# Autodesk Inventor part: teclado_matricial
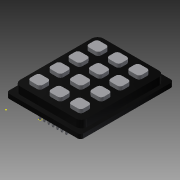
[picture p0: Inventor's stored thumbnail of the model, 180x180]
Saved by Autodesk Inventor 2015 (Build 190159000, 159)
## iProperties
Created: 2016-06
Part Number: teclado_matricial
Material: Genérico
Document SubType Name: Modeling
Designer: Diego
Density: 1 g/cm^3
Appearance: Valor por defecto
Author: Diego
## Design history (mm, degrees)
sketch "Boceto1"
  geometry: L1 (0, 0)-(51, 0); L2 (51, 0)-(51, 64); L3 (51, 64)-(0, 64); L4 (0, 64)-(0, 0)
  constraints: 8 end point, 2 parallel, 1 horizontal, 1 perpendicular
  dimensions: "d0" = 51 distance of L3.end L2.end; "d1" = 64 distance of L2.end L1.end
extrude "Extrusión1" new body sketch "Boceto1" distance "d2" = 3; taper "d3" = 0 deg
fillet "Empalme1" dims "d4" = 2
fillet "Empalme2" dims "d5" = 2
sketch "Boceto2"
  geometry: L1 (2.5, 32)-(2.5, 3.163); L2 (2.5, 3.163)-(48.5, 3.163); L3 (48.5, 3.163)-(48.5, 60.163); L4 (48.5, 60.163)-(2.5, 60.163); L5 (2.5, 60.163)-(2.5, 3.163); A1 r 2 centre (49, 62) between (51, 62) and (49, 64) reference; A2 r 2 centre (49, 2) between (49, 0) and (51, 2) reference; A3 r 2 centre (2, 62) between (2, 64) and (0, 62) reference; 1 further point
  constraints: 10 end point, 2 parallel, 1 horizontal, 1 perpendicular
  dimensions: "d7" = 46 distance of L4.end L3.end; "d8" = 57 distance of L3.end L2.end
extrude "Extrusión2" join sketch "Boceto2" distance "d9" = 5; taper "d10" = 0 deg
sketch "Boceto3" dims "d31" = 10, "d38" = 10
  geometry: L1 (2.5, 60.163)-(48.5, 60.163) reference; L2 (48.5, 3.163)-(2.5, 3.163) reference; L3 (2.5, 3.163)-(2.5, 60.163) reference; L4 (2.5, 31.663)-(48.5, 31.663); L5 (48.5, 60.163)-(48.5, 3.163) reference; L6 (25.5, 31.663)-(25.5, 38.163); L7 (21.25, 23.397)-(21.25, 26.913); L8 (23.25, 28.913)-(27.75, 28.913); L9 (29.75, 26.913)-(29.75, 23.413); L10 (27.75, 21.413)-(23.25, 21.413); L11 (41.75, 21.413)-(37.25, 21.413); L12 (43.75, 26.913)-(43.75, 23.413); L13 (37.25, 28.913)-(41.75, 28.913); L14 (35.25, 23.397)-(35.25, 26.913); L15 (27.75, 34.413)-(23.25, 34.413); L16 (29.75, 39.913)-(29.75, 36.413); L17 (23.25, 41.913)-(27.75, 41.913); L18 (21.25, 36.397)-(21.25, 39.913); L19 (41.75, 34.413)-(37.25, 34.413); L20 (43.75, 39.913)-(43.75, 36.413); L21 (37.25, 41.913)-(41.75, 41.913); L22 (35.25, 36.397)-(35.25, 39.913); L23 (27.75, 47.413)-(23.25, 47.413); L24 (29.75, 52.913)-(29.75, 49.413); L25 (23.25, 54.913)-(27.75, 54.913); L26 (21.25, 49.397)-(21.25, 52.913); L27 (41.75, 47.413)-(37.25, 47.413); L28 (43.75, 52.913)-(43.75, 49.413); L29 (37.25, 54.913)-(41.75, 54.913); L30 (35.25, 49.397)-(35.25, 52.913); L31 (35.25, 9.397)-(35.25, 12.913); L32 (41.75, 7.413)-(37.25, 7.413); L33 (37.25, 14.913)-(41.75, 14.913); L34 (43.75, 12.913)-(43.75, 9.413); L35 (21.25, 9.397)-(21.25, 12.913); L36 (23.25, 14.913)-(27.75, 14.913); L37 (29.75, 12.913)-(29.75, 9.413); L38 (27.75, 7.413)-(23.25, 7.413); L39 (13.75, 47.413)-(9.25, 47.413); L40 (15.75, 52.913)-(15.75, 49.413); L41 (7.25, 49.397)-(7.25, 52.913); L42 (9.25, 54.913)-(13.75, 54.913); L43 (7.25, 23.397)-(7.25, 26.913); L44 (9.25, 28.913)-(13.75, 28.913); L45 (15.75, 26.913)-(15.75, 23.413); L46 (13.75, 21.413)-(9.25, 21.413); L47 (11.5, 31.663)-(11.5, 38.163); L48 (13.75, 34.413)-(9.25, 34.413); L49 (15.75, 39.913)-(15.75, 36.413); L50 (9.25, 41.913)-(13.75, 41.913); L51 (7.25, 36.397)-(7.25, 39.913); L52 (15.75, 12.913)-(15.75, 9.413); L53 (9.25, 14.913)-(13.75, 14.913); L54 (13.75, 7.413)-(9.25, 7.413); L55 (7.25, 9.397)-(7.25, 12.913); L56 (6.5, 60.163)-(44.5, 60.163); L57 (48.5, 56.163)-(48.5, 7.163); L58 (44.5, 3.163)-(6.5, 3.163); L59 (2.5, 7.163)-(2.5, 56.163); A1 r 2 centre (23.25, 26.913) between (23.25, 28.913) and (21.25, 26.913); A2 r 2 centre (23.25, 23.413) between (21.25, 23.413) and (23.25, 21.413); A3 r 2 centre (27.75, 26.913) between (29.75, 26.913) and (27.75, 28.913); A4 r 2 centre (27.75, 23.413) between (27.75, 21.413) and (29.75, 23.413); A5 r 2 centre (41.75, 23.413) between (41.75, 21.413) and (43.75, 23.413); A6 r 2 centre (37.25, 23.413) between (35.25, 23.413) and (37.25, 21.413); A7 r 2 centre (37.25, 26.913) between (37.25, 28.913) and (35.25, 26.913); A8 r 2 centre (41.75, 26.913) between (43.75, 26.913) and (41.75, 28.913); A9 r 2 centre (27.75, 36.413) between (27.75, 34.413) and (29.75, 36.413); A10 r 2 centre (23.25, 36.413) between (21.25, 36.413) and (23.25, 34.413); A11 r 2 centre (23.25, 39.913) between (23.25, 41.913) and (21.25, 39.913); A12 r 2 centre (27.75, 39.913) between (29.75, 39.913) and (27.75, 41.913); A13 r 2 centre (41.75, 36.413) between (41.75, 34.413) and (43.75, 36.413); A14 r 2 centre (37.25, 36.413) between (35.25, 36.413) and (37.25, 34.413); A15 r 2 centre (37.25, 39.913) between (37.25, 41.913) and (35.25, 39.913); A16 r 2 centre (41.75, 39.913) between (43.75, 39.913) and (41.75, 41.913); A17 r 2 centre (27.75, 49.413) between (27.75, 47.413) and (29.75, 49.413); A18 r 2 centre (23.25, 49.413) between (21.25, 49.413) and (23.25, 47.413); A19 r 2 centre (23.25, 52.913) between (23.25, 54.913) and (21.25, 52.913); A20 r 2 centre (27.75, 52.913) between (29.75, 52.913) and (27.75, 54.913); A21 r 2 centre (41.75, 49.413) between (41.75, 47.413) and (43.75, 49.413); A22 r 2 centre (37.25, 49.413) between (35.25, 49.413) and (37.25, 47.413); A23 r 2 centre (37.25, 52.913) between (37.25, 54.913) and (35.25, 52.913); A24 r 2 centre (41.75, 52.913) between (43.75, 52.913) and (41.75, 54.913); A25 r 2 centre (37.25, 12.913) between (37.25, 14.913) and (35.25, 12.913); A26 r 2 centre (37.25, 9.413) between (35.25, 9.413) and (37.25, 7.413); A27 r 2 centre (41.75, 9.413) between (41.75, 7.413) and (43.75, 9.413); A28 r 2 centre (41.75, 12.913) between (43.75, 12.913) and (41.75, 14.913); A29 r 2 centre (23.25, 12.913) between (23.25, 14.913) and (21.25, 12.913); A30 r 2 centre (27.75, 12.913) between (29.75, 12.913) and (27.75, 14.913); A31 r 2 centre (23.25, 9.413) between (21.25, 9.413) and (23.25, 7.413); A32 r 2 centre (27.75, 9.413) between (27.75, 7.413) and (29.75, 9.413); A33 r 2 centre (13.75, 49.413) between (13.75, 47.413) and (15.75, 49.413); A34 r 2 centre (9.25, 49.413) between (7.25, 49.413) and (9.25, 47.413); A35 r 2 centre (13.75, 52.913) between (15.75, 52.913) and (13.75, 54.913); A36 r 2 centre (9.25, 52.913) between (9.25, 54.913) and (7.25, 52.913); A37 r 2 centre (9.25, 26.913) between (9.25, 28.913) and (7.25, 26.913); A38 r 2 centre (9.25, 23.413) between (7.25, 23.413) and (9.25, 21.413); A39 r 2 centre (13.75, 23.413) between (13.75, 21.413) and (15.75, 23.413); A40 r 2 centre (13.75, 26.913) between (15.75, 26.913) and (13.75, 28.913); A41 r 2 centre (13.75, 36.413) between (13.75, 34.413) and (15.75, 36.413); A42 r 2 centre (9.25, 36.413) between (7.25, 36.413) and (9.25, 34.413); A43 r 2 centre (9.25, 39.913) between (9.25, 41.913) and (7.25, 39.913); A44 r 2 centre (13.75, 39.913) between (15.75, 39.913) and (13.75, 41.913); A45 r 2 centre (13.75, 12.913) between (15.75, 12.913) and (13.75, 14.913); A46 r 2 centre (13.75, 9.413) between (13.75, 7.413) and (15.75, 9.413); A47 r 2 centre (9.25, 9.413) between (7.25, 9.413) and (9.25, 7.413); A48 r 2 centre (9.25, 12.913) between (9.25, 14.913) and (7.25, 12.913); A49 r 4 centre (6.5, 7.163) between (2.5, 7.163) and (6.5, 3.163); A50 r 4 centre (44.5, 7.163) between (44.5, 3.163) and (48.5, 7.163); A51 r 4 centre (44.5, 56.163) between (48.5, 56.163) and (44.5, 60.163); A52 r 4 centre (6.5, 56.163) between (6.5, 60.163) and (2.5, 56.163); 37 further points
  constraints: 116 point on circle, 110 end point, 64 point on line, 52 centre point, 15 tangent, 6 equal radius, 4 horizontal, 3 midpoint, 3 parallel, 3 vertical, 2 perpendicular, 267 other
  dimensions: "d15" = 8.5 distance of point (29.75, 21.413) point (21.25, 21.413); "d16" = 7.5 distance of point (29.75, 28.913) point (29.75, 21.413); "d20" = 14 distance of point (21.25, 21.413) point (35.25, 21.413); "d23" = 13 distance of point (21.25, 21.413) point (21.25, 34.413); "d28" = 14 distance of L14.start L31.start; "d35" = 14 distance of L23.start L39.start; "d41" = 4 radius of A49
extrude "Extrusión3" join sketch "Boceto3" distance "d42" = 2.5; taper "d43" = 0 deg
fillet "Empalme3" dims "d44" = 4
fillet "Empalme4" dims "d45" = 4
sketch "Boceto4" dims "d35" = 14, "d38" = 10
  geometry: L1 (-2, 0)-(-49, 0) reference; L2 (-25.5, 0)-(-25.5, 31.743); L3 (-14.434, 6)-(-36.434, 6); L4 (-36.434, 6)-(-36.434, 8); L5 (-36.434, 8)-(-14.434, 8); L6 (-14.434, 8)-(-14.434, 6); 1 further point
  constraints: 10 end point, 2 parallel, 1 horizontal, 1 midpoint, 1 perpendicular, 1 vertical
  dimensions: "d46" = 22 distance of L4.end L5.end; "d47" = 2 distance of L3.end L4.end
extrude "Extrusión4" join sketch "Boceto4" distance "d48" = 2.5; taper "d49" = 0 deg
sketch "Boceto5" dims "d61" = 10, "d68" = 10
  geometry: L1 (-36.434, 6)-(-14.434, 6) reference; L2 (-36.434, 8)-(-14.434, 8) reference; L3 (-24.784, 7)-(-24.784, 6.35); L4 (-24.784, 6.35)-(-26.084, 6.35); L5 (-26.084, 6.35)-(-26.084, 7.65); L6 (-26.084, 7.65)-(-24.784, 7.65); L7 (-24.784, 7.65)-(-24.784, 6.35); L8 (-25.434, 7)-(-15.828, 7); L9 (-21.784, 7)-(-21.784, 6.35); L10 (-21.784, 6.35)-(-23.084, 6.35); L11 (-23.084, 6.35)-(-23.084, 7.65); L12 (-23.084, 7.65)-(-21.784, 7.65); L13 (-21.784, 7.65)-(-21.784, 6.35); L14 (-18.784, 7)-(-18.784, 6.35); L15 (-18.784, 6.35)-(-20.084, 6.35); L16 (-20.084, 6.35)-(-20.084, 7.65); L17 (-20.084, 7.65)-(-18.784, 7.65); L18 (-18.784, 7.65)-(-18.784, 6.35); L19 (-15.784, 7)-(-15.784, 6.35); L20 (-15.784, 6.35)-(-17.084, 6.35); L21 (-17.084, 6.35)-(-17.084, 7.65); L22 (-17.084, 7.65)-(-15.784, 7.65); L23 (-15.784, 7.65)-(-15.784, 6.35); L24 (-27.784, 7)-(-27.784, 6.35); L25 (-27.784, 7.65)-(-27.784, 6.35); L26 (-27.784, 6.35)-(-29.084, 6.35); L27 (-29.084, 6.35)-(-29.084, 7.65); L28 (-29.084, 7.65)-(-27.784, 7.65); L29 (-30.784, 7)-(-30.784, 6.35); L30 (-30.784, 7.65)-(-30.784, 6.35); L31 (-30.784, 6.35)-(-32.084, 6.35); L32 (-32.084, 6.35)-(-32.084, 7.65); L33 (-32.084, 7.65)-(-30.784, 7.65); L34 (-33.784, 7)-(-33.784, 6.35); L35 (-33.784, 7.65)-(-33.784, 6.35); L36 (-33.784, 6.35)-(-35.084, 6.35); L37 (-35.084, 6.35)-(-35.084, 7.65); L38 (-35.084, 7.65)-(-33.784, 7.65); 7 further points
  constraints: 72 end point, 4 horizontal, 2 parallel, 1 perpendicular, 66 other
  dimensions: "d55" = 1.3 distance of L4.end L5.end; "d58" = 3 distance of L3.start L9.start; "d65" = 3 distance of L3.start L24.start
extrude "Extrusión5" join sketch "Boceto5" distance "d70" = 5; taper "d71" = 0 deg
fillet "Empalme5" dims "d72" = 0.2
sketch "Boceto6"
  geometry: 1 further point
node "Plano de trabajo1"
sketch "Boceto7" dims "d79" = 10
  geometry: L1 (-15.984, 7.65)-(-16.884, 7.65); L2 (-16.126, 6.691)-(-16.743, 6.691); L3 (-16.743, 6.691)-(-16.743, 7.309); L4 (-16.743, 7.309)-(-16.126, 7.309); L5 (-16.126, 7.309)-(-16.126, 6.691); L6 (-19.126, 6.691)-(-19.743, 6.691); L7 (-19.743, 7.309)-(-19.126, 7.309); L8 (-19.126, 7.309)-(-19.126, 6.691); L9 (-19.743, 6.691)-(-19.743, 7.309); L10 (-22.126, 6.691)-(-22.743, 6.691); L11 (-22.743, 7.309)-(-22.126, 7.309); L12 (-22.126, 7.309)-(-22.126, 6.691); L13 (-22.743, 6.691)-(-22.743, 7.309); L14 (-25.126, 6.691)-(-25.743, 6.691); L15 (-25.743, 7.309)-(-25.126, 7.309); L16 (-25.126, 7.309)-(-25.126, 6.691); L17 (-25.743, 6.691)-(-25.743, 7.309); L18 (-28.126, 6.691)-(-28.743, 6.691); L19 (-28.743, 7.309)-(-28.126, 7.309); L20 (-28.126, 7.309)-(-28.126, 6.691); L21 (-28.743, 6.691)-(-28.743, 7.309); L22 (-31.126, 6.691)-(-31.743, 6.691); L23 (-31.743, 7.309)-(-31.126, 7.309); L24 (-31.126, 7.309)-(-31.126, 6.691); L25 (-31.743, 6.691)-(-31.743, 7.309); L26 (-34.126, 6.691)-(-34.743, 6.691); L27 (-34.743, 7.309)-(-34.126, 7.309); L28 (-34.126, 7.309)-(-34.126, 6.691); L29 (-34.743, 6.691)-(-34.743, 7.309); 2 further points
  constraints: 58 end point, 2 horizontal, 2 parallel, 1 perpendicular, 48 other
  dimensions: "d76" = 3 distance of L3.end L7.start
feature "Solevación1" sketch "Boceto7" dims "d81" = 0, "d82" = 90 deg, "d83" = 0, "d84" = 90 deg
  node "Aristas1"
sketch "Boceto8" dims "d90" = 10
  geometry: L1 (-16.126, 6.691)-(-16.743, 6.691); L2 (-16.743, 6.691)-(-16.743, 7.309); L3 (-16.743, 7.309)-(-16.126, 7.309); L4 (-16.126, 7.309)-(-16.126, 6.691); L5 (-19.126, 6.691)-(-19.743, 6.691); L6 (-19.743, 6.691)-(-19.743, 7.309); L7 (-19.743, 7.309)-(-19.126, 7.309); L8 (-19.126, 7.309)-(-19.126, 6.691); L9 (-22.126, 6.691)-(-22.743, 6.691); L10 (-22.743, 6.691)-(-22.743, 7.309); L11 (-22.743, 7.309)-(-22.126, 7.309); L12 (-22.126, 7.309)-(-22.126, 6.691); L13 (-25.126, 6.691)-(-25.743, 6.691); L14 (-25.743, 6.691)-(-25.743, 7.309); L15 (-25.743, 7.309)-(-25.126, 7.309); L16 (-25.126, 7.309)-(-25.126, 6.691); L17 (-28.126, 6.691)-(-28.743, 6.691); L18 (-28.743, 6.691)-(-28.743, 7.309); L19 (-28.743, 7.309)-(-28.126, 7.309); L20 (-28.126, 7.309)-(-28.126, 6.691); L21 (-31.126, 6.691)-(-31.743, 6.691); L22 (-31.743, 6.691)-(-31.743, 7.309); L23 (-31.743, 7.309)-(-31.126, 7.309); L24 (-31.126, 7.309)-(-31.126, 6.691); L25 (-34.126, 6.691)-(-34.743, 6.691); L26 (-34.743, 6.691)-(-34.743, 7.309); L27 (-34.743, 7.309)-(-34.126, 7.309); L28 (-34.126, 7.309)-(-34.126, 6.691); 1 further point
  constraints: 56 end point, 2 horizontal, 2 parallel, 1 collinear, 1 perpendicular, 47 other
  dimensions: "d87" = 3 distance of L1.end L5.end
feature "Solevación2" sketch "Boceto8" dims "d92" = 0, "d93" = 90 deg, "d94" = 0, "d95" = 90 deg
  node "Aristas2"
sketch "Boceto9" dims "d101" = 10
  geometry: L1 (-19.743, 6.691)-(-19.583, 6.691) reference; L2 (-19.583, 6.691)-(-19.126, 6.691) reference; L3 (-19.126, 6.691)-(-19.126, 6.851) reference; L4 (-19.126, 6.851)-(-19.126, 7.309) reference; L5 (-19.126, 7.309)-(-19.253, 7.309) reference; L6 (-19.253, 7.309)-(-19.616, 7.309) reference; L7 (-19.616, 7.309)-(-19.743, 7.309) reference; L8 (-19.743, 7.309)-(-19.743, 6.691) reference; L9 (-19.126, 6.691)-(-19.743, 6.691); L10 (-19.743, 6.691)-(-19.743, 7.309); L11 (-19.743, 7.309)-(-19.126, 7.309); L12 (-19.126, 7.309)-(-19.126, 6.691); L13 (-22.126, 6.691)-(-22.743, 6.691); L14 (-22.743, 6.691)-(-22.743, 7.309); L15 (-22.743, 7.309)-(-22.126, 7.309); L16 (-22.126, 7.309)-(-22.126, 6.691); 7 further points
  constraints: 16 end point, 2 horizontal, 2 parallel, 1 perpendicular, 14 other
  dimensions: "d98" = 3 distance of L1.start point (-22.743, 6.691)
feature "Solevación3" sketch "Boceto9" dims "d103" = 0, "d104" = 90 deg, "d105" = 0, "d106" = 90 deg
  node "Aristas3"
sketch "Boceto10" dims "d112" = 10
  geometry: L1 (-25.884, 6.35)-(-24.984, 6.35) reference; L2 (-24.784, 6.55)-(-24.784, 7.45) reference; L3 (-24.984, 7.65)-(-25.884, 7.65) reference; L4 (-26.084, 7.45)-(-26.084, 6.55) reference; L5 (-22.743, 7.309)-(-22.095, 7.309); L6 (-22.095, 7.309)-(-22.095, 6.671); L7 (-22.095, 6.671)-(-22.743, 6.671); L8 (-22.743, 6.671)-(-22.743, 7.309); L9 (-25.743, 7.309)-(-25.095, 7.309); L10 (-25.095, 7.309)-(-25.095, 6.671); L11 (-25.095, 6.671)-(-25.743, 6.671); L12 (-25.743, 6.671)-(-25.743, 7.309); A1 r 0.2 centre (-25.884, 6.55) between (-26.084, 6.55) and (-25.884, 6.35) reference; A2 r 0.2 centre (-24.984, 6.55) between (-24.984, 6.35) and (-24.784, 6.55) reference; A3 r 0.2 centre (-24.984, 7.45) between (-24.784, 7.45) and (-24.984, 7.65) reference; A4 r 0.2 centre (-25.884, 7.45) between (-25.884, 7.65) and (-26.084, 7.45) reference; 1 further point
  constraints: 16 end point, 2 horizontal, 2 parallel, 1 collinear, 1 perpendicular, 7 other
  dimensions: "d109" = 3 distance of L6.end L10.end
feature "Solevación4" sketch "Boceto10" dims "d114" = 0, "d115" = 90 deg, "d116" = 0, "d117" = 90 deg
  node "Aristas4"
sketch "Boceto11"
  geometry: L1 (-28.884, 6.35)-(-27.984, 6.35) reference; L2 (-27.784, 6.55)-(-27.784, 7.45) reference; L3 (-27.984, 7.65)-(-28.884, 7.65) reference; L4 (-29.084, 7.45)-(-29.084, 6.55) reference; L5 (-25.743, 7.309)-(-25.084, 7.309); L6 (-25.084, 7.309)-(-25.084, 6.671); L7 (-25.084, 6.671)-(-25.743, 6.671); L8 (-25.743, 6.671)-(-25.743, 7.309); L9 (-25.743, 7.309)-(-25.084, 7.309); L10 (-25.084, 7.309)-(-25.084, 6.671); L11 (-25.084, 6.671)-(-25.743, 6.671); L12 (-25.743, 6.671)-(-25.743, 7.309); L13 (-25.743, 7.309)-(-25.084, 7.309); L14 (-25.084, 7.309)-(-25.084, 6.671); L15 (-25.084, 6.671)-(-25.743, 6.671); L16 (-25.743, 6.671)-(-25.743, 7.309); L17 (-25.743, 7.309)-(-25.095, 7.309); L18 (-25.095, 7.309)-(-25.095, 6.671); L19 (-25.095, 6.671)-(-25.743, 6.671); L20 (-25.743, 6.671)-(-25.743, 7.309); L21 (-25.743, 7.309)-(-25.095, 7.309); L22 (-25.095, 7.309)-(-25.095, 6.671); L23 (-25.095, 6.671)-(-25.743, 6.671); L24 (-25.743, 6.671)-(-25.743, 7.309); L25 (-27.784, 7.45)-(-27.784, 6.55) reference; L26 (-27.784, 7.061)-(-27.784, 7.382); L27 (-28.763, 6.671)-(-28.053, 6.671); L28 (-28.053, 6.671)-(-28.053, 7.382); L29 (-28.053, 7.382)-(-28.763, 7.382); L30 (-28.763, 7.382)-(-28.763, 6.671); A1 r 0.2 centre (-28.884, 6.55) between (-29.084, 6.55) and (-28.884, 6.35) reference; A2 r 0.2 centre (-27.984, 6.55) between (-27.984, 6.35) and (-27.784, 6.55) reference; A3 r 0.2 centre (-27.984, 7.45) between (-27.784, 7.45) and (-27.984, 7.65) reference; A4 r 0.2 centre (-28.884, 7.45) between (-28.884, 7.65) and (-29.084, 7.45) reference; 1 further point
  constraints: 50 end point, 12 parallel, 6 horizontal, 6 perpendicular, 2 point on line
  dimensions: "d119" = 0.321 distance of L26.start L26.end; "d120" = 0.71 distance of L29.end L28.end
extrude "Extrusión6" join sketch "Boceto11" distance "d121" = 1; taper "d122" = 0 deg
feature "Solevación5" dims "d123" = 0, "d124" = 90 deg, "d125" = 0, "d126" = 90 deg
  node "Aristas5"
  node "Aristas6"
sketch "Boceto12"
  geometry: 1 further point
sketch "Boceto13" dims "d134" = 10
  geometry: L1 (-28.763, 6.671)-(-28.053, 6.671); L2 (-28.053, 6.671)-(-28.053, 7.382); L3 (-28.053, 7.382)-(-28.763, 7.382); L4 (-28.763, 7.382)-(-28.763, 6.671); L5 (-31.884, 6.35)-(-30.984, 6.35) reference; L6 (-30.784, 6.55)-(-30.784, 7.45) reference; L7 (-30.984, 7.65)-(-31.884, 7.65) reference; L8 (-32.084, 7.45)-(-32.084, 6.55) reference; L9 (-31.763, 6.671)-(-31.053, 6.671); L10 (-31.053, 6.671)-(-31.053, 7.382); L11 (-31.053, 7.382)-(-31.763, 7.382); L12 (-31.763, 7.382)-(-31.763, 6.671); L13 (-34.053, 6.671)-(-34.053, 7.382); L14 (-34.763, 6.671)-(-34.053, 6.671); L15 (-34.053, 7.382)-(-34.763, 7.382); L16 (-34.763, 7.382)-(-34.763, 6.671); A1 r 0.2 centre (-31.884, 6.55) between (-32.084, 6.55) and (-31.884, 6.35) reference; A2 r 0.2 centre (-30.984, 6.55) between (-30.984, 6.35) and (-30.784, 6.55) reference; A3 r 0.2 centre (-30.984, 7.45) between (-30.784, 7.45) and (-30.984, 7.65) reference; A4 r 0.2 centre (-31.884, 7.45) between (-31.884, 7.65) and (-32.084, 7.45) reference; 7 further points
  constraints: 24 end point, 4 parallel, 3 horizontal, 2 perpendicular, 1 collinear, 13 other
  dimensions: "d131" = 3 distance of A2.centre point (-33.984, 6.55)
extrude "Extrusión7" join sketch "Boceto13" distance "d136" = 1; taper "d137" = 0 deg
feature "Solevación6" dims "d138" = 0, "d139" = 90 deg, "d140" = 0, "d141" = 90 deg
  node "Aristas7"
  node "Aristas8"
feature "Solevación7" dims "d142" = 0, "d143" = 90 deg, "d144" = 0, "d145" = 90 deg
  node "Aristas9"
  node "Aristas10"
node "Sólido1"
node "Contorno proyectado3"
node "Contorno proyectado4"
node "Contorno proyectado5"
node "Contorno proyectado6"
other parameters: "d73" = 1
